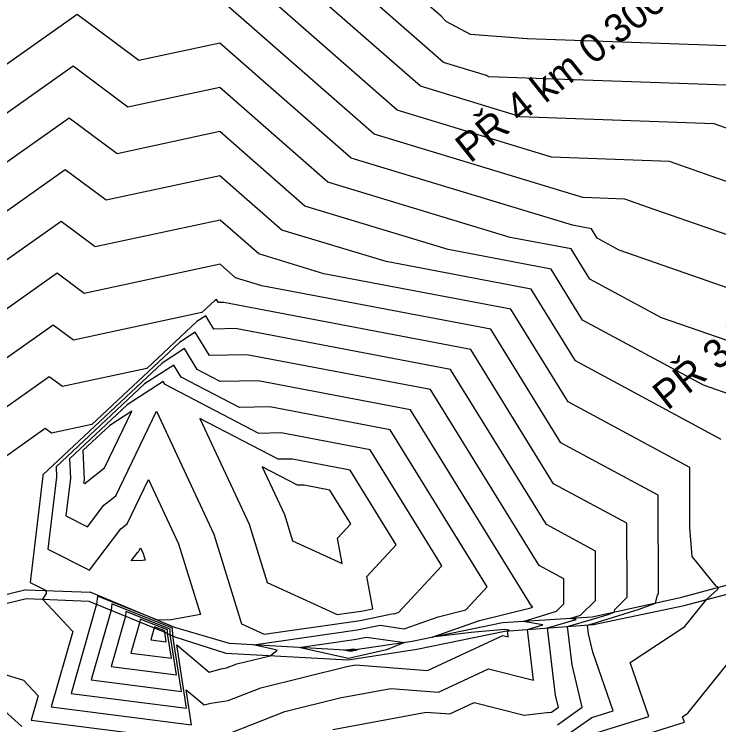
# Model space of a CAD drawing. Extents: x -549238 to -546764, y -1036895 to -1033794.
# Drawn here: x -548401.7 to -548178.9, y -1035524.7 to -1035300.1 of the extents above; entities that cross this region are included whole.
import ezdxf

# ---------------------------------------------------------------- set-up
doc = ezdxf.new("R2010")
doc.units = 0
for name, color, linetype in [('hlavni_vrst', 7, 'Continuous'), ('hrana_L', 7, 'Continuous'), ('norm_vrst', 7, 'Continuous'), ('x_popis_pricne_rezy_C12', 7, 'Continuous')]:
    doc.layers.add(name, color=color, linetype=linetype)

msp = doc.modelspace()

# ---------------------------------------------------------------- linework, layer by layer
at = {"layer": 'hlavni_vrst'}
for p, q in [((-548266.71, -1035300.68), (-548336.78, -1035239.3)), ((-548381.81, -1035300.17), (-548407.38, -1035318.19)), ((-548362.33, -1035314.7), (-548381.81, -1035300.17)), ((-548265.13, -1035302.38), (-548266.71, -1035300.68)), ((-548257.42, -1035306.51), (-548265.13, -1035302.38)), ((-548239.54, -1035307.83), (-548257.42, -1035306.51)), ((-548336.7, -1035309.2), (-548362.33, -1035314.7)), ((-548295.2, -1035345.56), (-548336.7, -1035309.2)), ((-548152.18, -1035310.9), (-548239.54, -1035307.83)), ((-548225.19, -1035366.76), (-548295.2, -1035345.56)), ((-548219.21, -1035367.9), (-548225.19, -1035366.76)), ((-548217.38, -1035370.86), (-548219.21, -1035367.9)), ((-548210.36, -1035374.64), (-548217.38, -1035370.86)), ((-548148.73, -1035396.14), (-548210.36, -1035374.64)), ((-548336.63, -1035379.11), (-548379.57, -1035388.33)), ((-548331.73, -1035383.41), (-548336.63, -1035379.11)), ((-548388.12, -1035381.95), (-548428.65, -1035410.51)), ((-548379.57, -1035388.33), (-548388.12, -1035381.95)), ((-548323.45, -1035385.91), (-548331.73, -1035383.41)), ((-548251.01, -1035399.66), (-548323.45, -1035385.91)), ((-548228.84, -1035435.52), (-548251.01, -1035399.66)), ((-548351.25, -1035410.95), (-548360.49, -1035416.91)), ((-548348.93, -1035414.74), (-548351.25, -1035410.95)), ((-548330.45, -1035424.34), (-548348.93, -1035414.74)), ((-548360.49, -1035416.91), (-548388.44, -1035443.11)), ((-548320.94, -1035424.19), (-548330.45, -1035424.34)), ((-548282.81, -1035431.42), (-548320.94, -1035424.19)), ((-548252.16, -1035481.01), (-548282.81, -1035431.42)), ((-548198.04, -1035452.13), (-548228.84, -1035435.52)), ((-548388.44, -1035443.11), (-548388.33, -1035446.34)), ((-548388.33, -1035446.34), (-548391.06, -1035469.16)), ((-548366.02, -1035461.13), (-548359.26, -1035447.11)), ((-548359.26, -1035447.11), (-548349.79, -1035467.47)), ((-548197.94, -1035483.23), (-548198.04, -1035452.13)), ((-548368.01, -1035462.7), (-548366.02, -1035461.13)), ((-548377.98, -1035475.8), (-548368.01, -1035462.7)), ((-548391.06, -1035469.16), (-548377.98, -1035475.8)), ((-548349.79, -1035467.47), (-548342.87, -1035489.84)), ((-548258.92, -1035488.34), (-548252.16, -1035481.01)), ((-548375.38, -1035484.01), (-548375.68, -1035486.56)), ((-548356.35, -1035491.63), (-548375.38, -1035484.01)), ((-548198.87, -1035486.25), (-548198.29, -1035483.58)), ((-548198.29, -1035483.58), (-548197.94, -1035483.23)), ((-548375.68, -1035486.56), (-548383.73, -1035514.73)), ((-548204.13, -1035488.14), (-548198.87, -1035486.25)), ((-548267.66, -1035490.52), (-548258.92, -1035488.34)), ((-548218.62, -1035492.6), (-548204.13, -1035488.14)), ((-548352.09, -1035491.46), (-548356.35, -1035491.63)), ((-548342.87, -1035489.84), (-548352.09, -1035491.46)), ((-548278.38, -1035494.31), (-548267.66, -1035490.52)), ((-548293.25, -1035494.7), (-548286.05, -1035493.2)), ((-548286.05, -1035493.2), (-548278.38, -1035494.31)), ((-548220.44, -1035493.13), (-548218.62, -1035492.6)), ((-548220.1, -1035495.92), (-548220.44, -1035493.13)), ((-548326.04, -1035499.43), (-548293.25, -1035494.7)), ((-548218.72, -1035501.7), (-548220.1, -1035495.92)), ((-548350.36, -1035499.41), (-548340.11, -1035508.02)), ((-548347.23, -1035519.39), (-548350.36, -1035499.41)), ((-548318.57, -1035501.07), (-548326.04, -1035499.43)), ((-548331.36, -1035505.43), (-548320.75, -1035502.82)), ((-548320.75, -1035502.82), (-548318.57, -1035501.07)), ((-548212.33, -1035520.2), (-548218.72, -1035501.7)), ((-548340.11, -1035508.02), (-548336.27, -1035506.94)), ((-548336.27, -1035506.94), (-548334.55, -1035506.69)), ((-548334.55, -1035506.69), (-548331.36, -1035505.43)), ((-548383.73, -1035514.73), (-548347.23, -1035519.39)), ((-548219.07, -1035522.32), (-548212.33, -1035520.2)), ((-548228.08, -1035528.71), (-548219.07, -1035522.32))]:
    msp.add_line(p, q, dxfattribs=at)
at = {"layer": 'hrana_L'}
for p, q in [((-548117.3, -1035464.61), (-548191.5, -1035484.65)), ((-548189.89, -1035486.99), (-548118.94, -1035468.07)), ((-548397.94, -1035481.98), (-548424.88, -1035488.54)), ((-548397.94, -1035481.98), (-548377.67, -1035482.78)), ((-548350.91, -1035493.89), (-548377.67, -1035482.78)), ((-548424.09, -1035491.03), (-548397.82, -1035484.75)), ((-548397.82, -1035484.75), (-548378.09, -1035485.58)), ((-548191.5, -1035484.65), (-548219, -1035490.61)), ((-548378.09, -1035485.58), (-548354.63, -1035495.14)), ((-548218.54, -1035492.99), (-548189.89, -1035486.99)), ((-548219, -1035490.61), (-548247.31, -1035492.39)), ((-548333.62, -1035498.99), (-548350.91, -1035493.89)), ((-548247.31, -1035492.39), (-548275.92, -1035498.32)), ((-548246.59, -1035495.02), (-548218.54, -1035492.99)), ((-548354.63, -1035495.14), (-548350.9, -1035496.85)), ((-548274.43, -1035500.8), (-548246.59, -1035495.02)), ((-548350.9, -1035496.85), (-548334.77, -1035502.05)), ((-548275.92, -1035498.32), (-548295.3, -1035501.2)), ((-548428.68, -1035498.83), (-548399.35, -1035525.24)), ((-548295.3, -1035501.2), (-548333.62, -1035498.99)), ((-548334.77, -1035502.05), (-548296.13, -1035504.17)), ((-548296.13, -1035504.17), (-548274.43, -1035500.8))]:
    msp.add_line(p, q, dxfattribs=at)
at = {"layer": 'norm_vrst'}
for p, q in [((-548265.98, -1035315.28), (-548336.76, -1035253.28)), ((-548273.28, -1035322.85), (-548336.75, -1035267.26)), ((-548280.59, -1035330.42), (-548336.73, -1035281.24)), ((-548287.89, -1035337.99), (-548336.72, -1035295.22)), ((-548383.07, -1035316.52), (-548411.64, -1035336.65)), ((-548365.77, -1035329.43), (-548383.07, -1035316.52)), ((-548252.37, -1035319.41), (-548265.98, -1035315.28)), ((-548251.77, -1035319.8), (-548252.37, -1035319.41)), ((-548166.28, -1035322.8), (-548251.77, -1035319.8)), ((-548336.69, -1035323.19), (-548365.77, -1035329.43)), ((-548302.5, -1035353.13), (-548336.69, -1035323.19)), ((-548242.22, -1035332.26), (-548273.28, -1035322.85)), ((-548232.08, -1035345.12), (-548280.59, -1035330.42)), ((-548241.79, -1035332.54), (-548242.22, -1035332.26)), ((-548384.33, -1035332.88), (-548415.89, -1035355.12)), ((-548369.22, -1035344.15), (-548384.33, -1035332.88)), ((-548180.38, -1035334.7), (-548241.79, -1035332.54)), ((-548137.55, -1035349.93), (-548180.38, -1035334.7)), ((-548336.67, -1035337.17), (-548369.22, -1035344.15)), ((-548309.81, -1035360.7), (-548336.67, -1035337.17)), ((-548221.93, -1035357.97), (-548287.89, -1035337.99)), ((-548231.81, -1035345.29), (-548232.08, -1035345.12)), ((-548194.49, -1035346.6), (-548231.81, -1035345.29)), ((-548168.45, -1035355.86), (-548194.49, -1035346.6)), ((-548385.59, -1035349.23), (-548420.14, -1035373.58)), ((-548372.67, -1035358.88), (-548385.59, -1035349.23)), ((-548336.66, -1035351.15), (-548372.67, -1035358.88)), ((-548317.11, -1035368.27), (-548336.66, -1035351.15)), ((-548244.85, -1035370.59), (-548302.5, -1035353.13)), ((-548221.84, -1035358.03), (-548221.93, -1035357.97)), ((-548208.59, -1035358.5), (-548221.84, -1035358.03)), ((-548199.35, -1035361.78), (-548208.59, -1035358.5)), ((-548264.5, -1035374.42), (-548309.81, -1035360.7)), ((-548138.95, -1035382.85), (-548199.35, -1035361.78)), ((-548386.85, -1035365.59), (-548424.4, -1035392.05)), ((-548376.12, -1035373.6), (-548386.85, -1035365.59)), ((-548336.64, -1035365.13), (-548376.12, -1035373.6)), ((-548324.42, -1035375.84), (-548336.64, -1035365.13)), ((-548284.15, -1035378.25), (-548317.11, -1035368.27)), ((-548225.57, -1035374.25), (-548244.85, -1035370.59)), ((-548231.93, -1035380.6), (-548264.5, -1035374.42)), ((-548219.67, -1035383.79), (-548225.57, -1035374.25)), ((-548303.8, -1035382.08), (-548324.42, -1035375.84)), ((-548238.29, -1035386.96), (-548284.15, -1035378.25)), ((-548221.97, -1035396.72), (-548231.93, -1035380.6)), ((-548244.65, -1035393.31), (-548303.8, -1035382.08)), ((-548197.06, -1035395.99), (-548219.67, -1035383.79)), ((-548224.26, -1035409.65), (-548238.29, -1035386.96)), ((-548338.44, -1035390.65), (-548342.37, -1035394.33)), ((-548337.73, -1035390.19), (-548338.44, -1035390.65)), ((-548337.1, -1035391.23), (-548337.73, -1035390.19)), ((-548335.42, -1035391.2), (-548337.1, -1035391.23)), ((-548257.37, -1035406.01), (-548335.42, -1035391.2)), ((-548342.37, -1035394.33), (-548383.02, -1035403.05)), ((-548226.55, -1035422.58), (-548244.65, -1035393.31)), ((-548343.95, -1035397.21), (-548359.78, -1035412.05)), ((-548341.11, -1035395.38), (-548343.95, -1035397.21)), ((-548338.56, -1035399.56), (-548341.11, -1035395.38)), ((-548183.76, -1035417.33), (-548221.97, -1035396.72)), ((-548158.51, -1035409.43), (-548197.06, -1035395.99)), ((-548389.38, -1035398.3), (-548432.9, -1035428.98)), ((-548383.02, -1035403.05), (-548389.38, -1035398.3)), ((-548331.8, -1035399.45), (-548338.56, -1035399.56)), ((-548263.73, -1035412.37), (-548331.8, -1035399.45)), ((-548344.49, -1035400.57), (-548349.46, -1035403.78)), ((-548340.02, -1035407.89), (-548344.49, -1035400.57)), ((-548349.46, -1035403.78), (-548377.2, -1035429.77)), ((-548347.87, -1035405.76), (-548354.98, -1035410.35)), ((-548343.84, -1035412.35), (-548347.87, -1035405.76)), ((-548231.14, -1035448.45), (-548257.37, -1035406.01)), ((-548328.18, -1035407.69), (-548340.02, -1035407.89)), ((-548270.09, -1035418.72), (-548328.18, -1035407.69)), ((-548354.98, -1035410.35), (-548392.67, -1035445.67)), ((-548178.13, -1035434.53), (-548224.26, -1035409.65)), ((-548359.78, -1035412.05), (-548386.46, -1035417.78)), ((-548336.56, -1035416.13), (-548343.84, -1035412.35)), ((-548233.43, -1035461.38), (-548263.73, -1035412.37)), ((-548390.64, -1035414.66), (-548437.15, -1035447.44)), ((-548386.46, -1035417.78), (-548390.64, -1035414.66)), ((-548354.63, -1035416.14), (-548366, -1035423.48)), ((-548354.03, -1035417.12), (-548354.63, -1035416.14)), ((-548324.33, -1035432.55), (-548354.03, -1035417.12)), ((-548324.56, -1035415.94), (-548336.56, -1035416.13)), ((-548276.45, -1035425.07), (-548324.56, -1035415.94)), ((-548168.3, -1035422.73), (-548183.76, -1035417.33)), ((-548235.72, -1035474.31), (-548270.09, -1035418.72)), ((-548366, -1035423.48), (-548384.22, -1035440.55)), ((-548188.09, -1035443.33), (-548226.55, -1035422.58)), ((-548373.19, -1035443.45), (-548364.58, -1035425.57)), ((-548364.58, -1035425.57), (-548371.51, -1035430.05)), ((-548369.61, -1035452.29), (-548356.71, -1035425.52)), ((-548356.71, -1035425.52), (-548338.61, -1035464.39)), ((-548238.01, -1035487.24), (-548276.45, -1035425.07)), ((-548318.22, -1035440.75), (-548342.99, -1035427.89)), ((-548342.99, -1035427.89), (-548327.44, -1035461.3)), ((-548391.9, -1035431.02), (-548441.41, -1035465.9)), ((-548389.91, -1035432.5), (-548391.9, -1035431.02)), ((-548377.2, -1035429.77), (-548389.91, -1035432.5)), ((-548371.51, -1035430.05), (-548379.99, -1035437.99)), ((-548317.31, -1035432.43), (-548324.33, -1035432.55)), ((-548289.17, -1035437.78), (-548317.31, -1035432.43)), ((-548266.54, -1035474.38), (-548289.17, -1035437.78)), ((-548379.99, -1035437.99), (-548379.66, -1035447.15)), ((-548384.22, -1035440.55), (-548383.99, -1035446.75)), ((-548313.69, -1035440.68), (-548318.22, -1035440.75)), ((-548295.53, -1035444.13), (-548313.69, -1035440.68)), ((-548378.79, -1035447.86), (-548373.19, -1035443.45)), ((-548312.11, -1035448.96), (-548323.27, -1035443.16)), ((-548323.27, -1035443.16), (-548316.26, -1035458.22)), ((-548280.92, -1035467.75), (-548295.53, -1035444.13)), ((-548188.02, -1035462.34), (-548188.09, -1035443.33)), ((-548392.66, -1035445.94), (-548396.7, -1035479.67)), ((-548392.67, -1035445.67), (-548392.66, -1035445.94)), ((-548383.99, -1035446.75), (-548385.42, -1035458.65)), ((-548379.66, -1035447.15), (-548379.78, -1035448.14)), ((-548379.78, -1035448.14), (-548379.21, -1035448.42)), ((-548379.21, -1035448.42), (-548378.79, -1035447.86)), ((-548310.07, -1035448.93), (-548312.11, -1035448.96)), ((-548301.89, -1035450.48), (-548310.07, -1035448.93)), ((-548208, -1035460.93), (-548231.14, -1035448.45)), ((-548295.31, -1035461.12), (-548301.89, -1035450.48)), ((-548373.4, -1035455.28), (-548369.61, -1035452.29)), ((-548378.6, -1035462.11), (-548373.4, -1035455.28)), ((-548385.42, -1035458.65), (-548378.6, -1035462.11)), ((-548316.26, -1035458.22), (-548313.71, -1035466.48)), ((-548327.44, -1035461.3), (-548321.77, -1035479.64)), ((-548299.49, -1035465.66), (-548295.31, -1035461.12)), ((-548217.95, -1035469.73), (-548233.43, -1035461.38)), ((-548207.92, -1035484.29), (-548208, -1035460.93)), ((-548187.36, -1035471.47), (-548188.02, -1035462.34)), ((-548338.61, -1035464.39), (-548329.83, -1035492.8)), ((-548313.71, -1035466.48), (-548298, -1035473.7)), ((-548298, -1035473.7), (-548299.49, -1035465.66)), ((-548362.44, -1035469.98), (-548361.82, -1035468.7)), ((-548361.82, -1035468.7), (-548360.96, -1035470.55)), ((-548290.21, -1035477.82), (-548280.92, -1035467.75)), ((-548364.72, -1035472.88), (-548362.62, -1035470.12)), ((-548362.62, -1035470.12), (-548362.44, -1035469.98)), ((-548360.96, -1035470.55), (-548360.33, -1035472.59)), ((-548217.9, -1035485.35), (-548217.95, -1035469.73)), ((-548179.72, -1035480.84), (-548187.36, -1035471.47)), ((-548361.17, -1035472.73), (-548364.72, -1035472.88)), ((-548360.33, -1035472.59), (-548361.17, -1035472.73)), ((-548280.21, -1035489.2), (-548266.54, -1035474.38)), ((-548227.91, -1035478.53), (-548235.72, -1035474.31)), ((-548288.31, -1035488.02), (-548290.21, -1035477.82)), ((-548396.7, -1035479.67), (-548391.66, -1035482.23)), ((-548321.77, -1035479.64), (-548299.57, -1035489.83)), ((-548227.88, -1035486.42), (-548227.91, -1035478.53)), ((-548391.66, -1035482.23), (-548391.61, -1035483.13)), ((-548182.77, -1035485.09), (-548179.17, -1035481.83)), ((-548179.04, -1035481.28), (-548179.72, -1035480.84)), ((-548179.17, -1035481.83), (-548179.04, -1035481.28)), ((-548391.61, -1035483.13), (-548392.81, -1035484.96)), ((-548392.81, -1035484.96), (-548383.21, -1035495.14)), ((-548211.83, -1035488.17), (-548207.92, -1035484.29)), ((-548370.89, -1035486.42), (-548371.12, -1035488.42)), ((-548351.63, -1035494.13), (-548370.89, -1035486.42)), ((-548237.86, -1035487.32), (-548238.01, -1035487.24)), ((-548230.25, -1035488.77), (-548227.88, -1035486.42)), ((-548222.6, -1035490.02), (-548217.9, -1035485.35)), ((-548186.7, -1035489.89), (-548182.77, -1035485.09)), ((-548371.12, -1035488.42), (-548377.43, -1035510.49)), ((-548366.4, -1035488.83), (-548366.56, -1035490.28)), ((-548352.46, -1035494.41), (-548366.4, -1035488.83)), ((-548299.57, -1035489.83), (-548291.35, -1035488.65)), ((-548292.3, -1035491.67), (-548281.75, -1035489.47)), ((-548291.35, -1035488.65), (-548288.31, -1035488.02)), ((-548281.75, -1035489.47), (-548281.31, -1035489.54)), ((-548281.31, -1035489.54), (-548280.71, -1035489.32)), ((-548280.71, -1035489.32), (-548280.21, -1035489.2)), ((-548254.62, -1035491.72), (-548238.38, -1035487.67)), ((-548240.79, -1035491.98), (-548230.25, -1035488.77)), ((-548238.38, -1035487.67), (-548237.91, -1035487.52)), ((-548237.91, -1035487.52), (-548237.86, -1035487.48)), ((-548237.86, -1035487.48), (-548237.86, -1035487.32)), ((-548213.85, -1035489.75), (-548212.03, -1035489.1)), ((-548212.03, -1035489.1), (-548211.83, -1035488.17)), ((-548366.56, -1035490.28), (-548371.13, -1035506.25)), ((-548361.91, -1035491.24), (-548362.01, -1035492.13)), ((-548353.29, -1035494.69), (-548361.91, -1035491.24)), ((-548322.73, -1035496.06), (-548292.3, -1035491.67)), ((-548269.56, -1035497), (-548254.62, -1035491.72)), ((-548233.1, -1035494.04), (-548223.99, -1035491.41)), ((-548226.77, -1035493.59), (-548218.87, -1035491.3)), ((-548225.97, -1035491.05), (-548222.6, -1035490.02)), ((-548223.99, -1035491.41), (-548225.97, -1035491.05)), ((-548218.87, -1035491.3), (-548213.85, -1035489.75)), ((-548189.65, -1035493.57), (-548186.7, -1035489.89)), ((-548362.01, -1035492.13), (-548364.83, -1035502.01)), ((-548357.45, -1035493.99), (-548358.54, -1035497.77)), ((-548357.41, -1035493.65), (-548357.45, -1035493.99)), ((-548354.12, -1035494.97), (-548357.41, -1035493.65)), ((-548329.83, -1035492.8), (-548322.73, -1035496.06)), ((-548234.6, -1035493.1), (-548240.79, -1035491.98)), ((-548239.44, -1035494.5), (-548234.6, -1035493.1)), ((-548225.31, -1035505.67), (-548226.77, -1035493.59)), ((-548206.95, -1035504.99), (-548189.65, -1035493.57)), ((-548383.21, -1035495.14), (-548390.03, -1035518.97)), ((-548354.11, -1035495.38), (-548354.12, -1035494.97)), ((-548353.64, -1035498.39), (-548354.11, -1035495.38)), ((-548353.27, -1035495.76), (-548353.29, -1035494.69)), ((-548352.03, -1035503.64), (-548353.27, -1035495.76)), ((-548352.43, -1035496.15), (-548352.46, -1035494.41)), ((-548350.43, -1035508.89), (-548352.43, -1035496.15)), ((-548351.59, -1035496.53), (-548351.63, -1035494.13)), ((-548257.17, -1035495.45), (-548269.56, -1035497)), ((-548246.73, -1035494.52), (-548257.17, -1035495.45)), ((-548245.21, -1035494.8), (-548246.73, -1035494.52)), ((-548245.77, -1035494.96), (-548245.21, -1035494.8)), ((-548245.54, -1035496.81), (-548245.77, -1035494.96)), ((-548237.49, -1035510.59), (-548239.44, -1035494.5)), ((-548230.52, -1035515.42), (-548233.1, -1035494.04)), ((-548358.54, -1035497.77), (-548353.64, -1035498.39)), ((-548348.83, -1035514.14), (-548351.59, -1035496.53)), ((-548311.74, -1035500.25), (-548294.21, -1035497.72)), ((-548294.21, -1035497.72), (-548290.35, -1035496.92)), ((-548290.35, -1035496.92), (-548278.29, -1035498.67)), ((-548271.01, -1035507.52), (-548247.18, -1035496.4)), ((-548247.18, -1035496.4), (-548245.54, -1035496.81)), ((-548296, -1035503.71), (-548311.74, -1035500.25)), ((-548297.44, -1035501.08), (-548295.16, -1035500.75)), ((-548295.16, -1035500.75), (-548294.65, -1035500.64)), ((-548294.65, -1035500.64), (-548293.08, -1035500.87)), ((-548278.29, -1035498.67), (-548284.03, -1035500.98)), ((-548364.83, -1035502.01), (-548352.03, -1035503.64)), ((-548295.39, -1035501.53), (-548297.44, -1035501.08)), ((-548284.03, -1035500.98), (-548296, -1035503.71)), ((-548293.83, -1035501.17), (-548295.39, -1035501.53)), ((-548293.08, -1035500.87), (-548293.83, -1035501.17)), ((-548188.67, -1035521), (-548173.43, -1035501.96)), ((-548201.06, -1035522.01), (-548206.95, -1035504.99)), ((-548413.16, -1035506.15), (-548398.79, -1035510.52)), ((-548371.13, -1035506.25), (-548350.43, -1035508.89)), ((-548323.77, -1035512.95), (-548296.59, -1035506.26)), ((-548296.59, -1035506.26), (-548293.78, -1035505.74)), ((-548293.78, -1035505.74), (-548271.01, -1035507.52)), ((-548267.52, -1035514.38), (-548251.74, -1035507.02)), ((-548251.74, -1035507.02), (-548237.49, -1035510.59)), ((-548222.1, -1035519.12), (-548225.31, -1035505.67)), ((-548398.79, -1035510.52), (-548394.12, -1035515.48)), ((-548377.43, -1035510.49), (-548348.83, -1035514.14)), ((-548347.35, -1035513.66), (-548341.71, -1035518.39)), ((-548345.62, -1035524.64), (-548347.35, -1035513.66)), ((-548334.06, -1035517.01), (-548323.77, -1035512.95)), ((-548298.78, -1035516.19), (-548282.59, -1035513.2)), ((-548282.59, -1035513.2), (-548267.52, -1035514.38)), ((-548394.12, -1035515.48), (-548396.33, -1035523.21)), ((-548316.18, -1035520.47), (-548298.78, -1035516.19)), ((-548229.64, -1035519.13), (-548230.52, -1035515.42)), ((-548341.71, -1035518.39), (-548339.6, -1035517.79)), ((-548339.6, -1035517.79), (-548334.06, -1035517.01)), ((-548264.02, -1035521.24), (-548256.3, -1035517.64)), ((-548256.3, -1035517.64), (-548240.49, -1035521.6)), ((-548390.03, -1035518.97), (-548345.62, -1035524.64)), ((-548333.58, -1035527.33), (-548316.18, -1035520.47)), ((-548300.96, -1035526.11), (-548271.41, -1035520.66)), ((-548271.41, -1035520.66), (-548264.02, -1035521.24)), ((-548240.49, -1035521.6), (-548233.3, -1035520.74)), ((-548233.3, -1035520.74), (-548233.19, -1035520.75)), ((-548233.19, -1035520.75), (-548231.79, -1035520.66)), ((-548231.79, -1035520.66), (-548229.64, -1035519.13)), ((-548229.94, -1035524.69), (-548222.1, -1035519.12)), ((-548396.33, -1035523.21), (-548344.02, -1035529.89)), ((-548219.05, -1035527.64), (-548201.06, -1035522.01)), ((-548190.38, -1035522.13), (-548188.67, -1035521)), ((-548189.8, -1035523.82), (-548190.38, -1035522.13)), ((-548219.02, -1035532.97), (-548189.8, -1035523.82))]:
    msp.add_line(p, q, dxfattribs=at)

# ---------------------------------------------------------------- texts
at = {"layer": 'x_popis_pricne_rezy_C12'}
for s, p in [('PŘ 4 km 0.3000', (-548257.52, -1035347.36)), ('PŘ 3 km 0.2000', (-548195.12, -1035425.5))]:
    msp.add_text(s, height=9.0627, rotation=38.6103, dxfattribs=at).set_placement(p)

doc.saveas('drawing.dxf')
